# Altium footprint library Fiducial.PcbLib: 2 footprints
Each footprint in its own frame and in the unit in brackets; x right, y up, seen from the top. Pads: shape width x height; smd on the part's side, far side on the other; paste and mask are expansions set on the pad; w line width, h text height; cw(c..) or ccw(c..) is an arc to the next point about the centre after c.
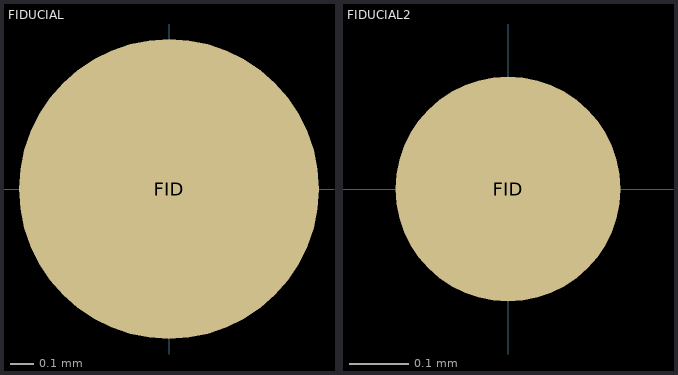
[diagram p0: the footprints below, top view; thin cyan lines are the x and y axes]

## FIDUCIAL [mil] "Fiducial marker"
pads (1):
  round 50 smd paste-50: FID(0,0)

## FIDUCIAL2 [mil] "Fiducial marker"
pads (1):
  round 15 smd: FID(0,0)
